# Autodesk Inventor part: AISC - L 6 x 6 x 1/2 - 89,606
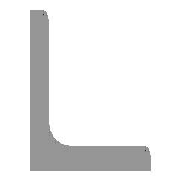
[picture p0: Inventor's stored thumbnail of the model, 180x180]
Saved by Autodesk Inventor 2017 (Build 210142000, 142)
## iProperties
_CCFamilyMember: 47
_CCFamilyDisplayName: ANSI L (Kątownik równoramienny) - Kątownik — Rozmiary w nawiasach zostały wycofane
_FrameMemberDoc: Frame Member File
_Version: 15.0.0
_GetPNFromCC: 1
Created: 2016-02
Part Number: AISC - L 6 x 6 x 1/2 - 89,606
Material: Stal, miękka
Description: Kątownik
Document SubType Name: Modeling
Standard: ANSI
Designer: X
Standards Organization: ANSI
Language: pl-PL
Size Designation: L 6 x 6 x 1/2
Categories: <MemberInstance><Categories><Category DisplayName="Kształtowniki konstrukcyjne" InternalName="089c4875-fa83-4c05-b084-43b9cc11f5ed" Mnemonic="GRDR"><CategoryPar
Stock Number: L 6 x 6 x 1/2
Density: 7.85 g/cm^3
Appearance: Częściowo polerowana
IsCustomPart: 1
G_L: 2276,000 mm
G_W: 152,400 mm
G_H: 152,400 mm
Author: X
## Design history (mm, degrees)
node "Płaszczyzna początkowa"
node "Płaszczyzna końcowa"
sketch "Szkic"
  geometry: L1 (152.4, 0)-(0, 0); L2 (0, 0)-(0, 152.4); L3 (0, 152.4)-(6.35, 152.4); L4 (12.7, 146.05)-(12.7, 25.4); L5 (25.4, 12.7)-(146.05, 12.7); L6 (152.4, 6.35)-(152.4, 0); L7 (0, -11.041)-(0, 31.538); L8 (-11.041, 0)-(31.538, 0); L9 (0, 186.666)-(0, -43.993) reference; L10 (-43.993, 0)-(186.666, 0) reference; A1 r 12.7 centre (25.4, 25.4) between (12.7, 25.4) and (25.4, 12.7); A2 r 6.35 centre (6.35, 146.05) between (12.7, 146.05) and (6.35, 152.4); A3 r 6.35 centre (146.05, 6.35) between (152.4, 6.35) and (146.05, 12.7); 3 further points
  constraints: 16 end point, 6 point on circle, 6 point on line, 6 tangent, 4 parallel, 3 centre point, 2 collinear, 1 equal radius, 1 horizontal, 1 perpendicular
  dimensions: "d0" = 152.4 distance between parallel lines of L6 L2 (= G_H); "d1" = 152.4 distance between parallel lines of L3 L1 (= G_H); "d2" = 12.7 distance between parallel lines of L2 L4 (= G_T); "d3" = 12.7 distance between parallel lines of L1 L5 (= G_T); "d10" = 0 distance between parallel lines of L7 L2 (computed from ex); "d11" = 0 distance between parallel lines of L8 L1 (computed from d10); "d14" = 12.7 radius of A1 (= G_IR); "d15" = 6.35 radius of A2 (= G_ER)
extrude "Bryła" new body sketch "Szkic" stored distance "d4" = 2276 (= G_L); taper "d5" = 0 deg
node "Driven Length"
  sketch "Sketch3"
    geometry: L1 (0, 0)-(10, 0) reference
    constraints: 2 end point, 1 horizontal
  workplane "Work Plane3"
  sketch "Sketch4"
    geometry: L1 (-2, -153)-(12, -153) reference; L2 (-2, 2123)-(12, 2123) reference
    dimensions: "d17" = 2276 distance between parallel lines of L1 L2 (derived)
body "Solid1"
other parameters: "G_H" = 152.4 [user parameter; used in 2 equation terms], "G_T" = 12.7 [user parameter; used in 2 equation terms], "G_ER" = 6.35 [user parameter; used in 1 equation term], "G_IR" = 12.7 [user parameter; used in 1 equation term], "G_L" = 2276 (= d17) [user parameter; used in 1 equation term], "ex" = 0 [user parameter; used in 1 equation term], "G_OFFSET_START" = 153 [user parameter; used in 1 equation term], "G_OFFSET_END" = 153 [user parameter; used in 1 equation term], "d12" = -153 (= -G_OFFSET_START), "d13" = 2123 (= G_OFFSET_END + B_L), "d16" = 90 deg, "MAS" = 2.9168 [user parameter]
